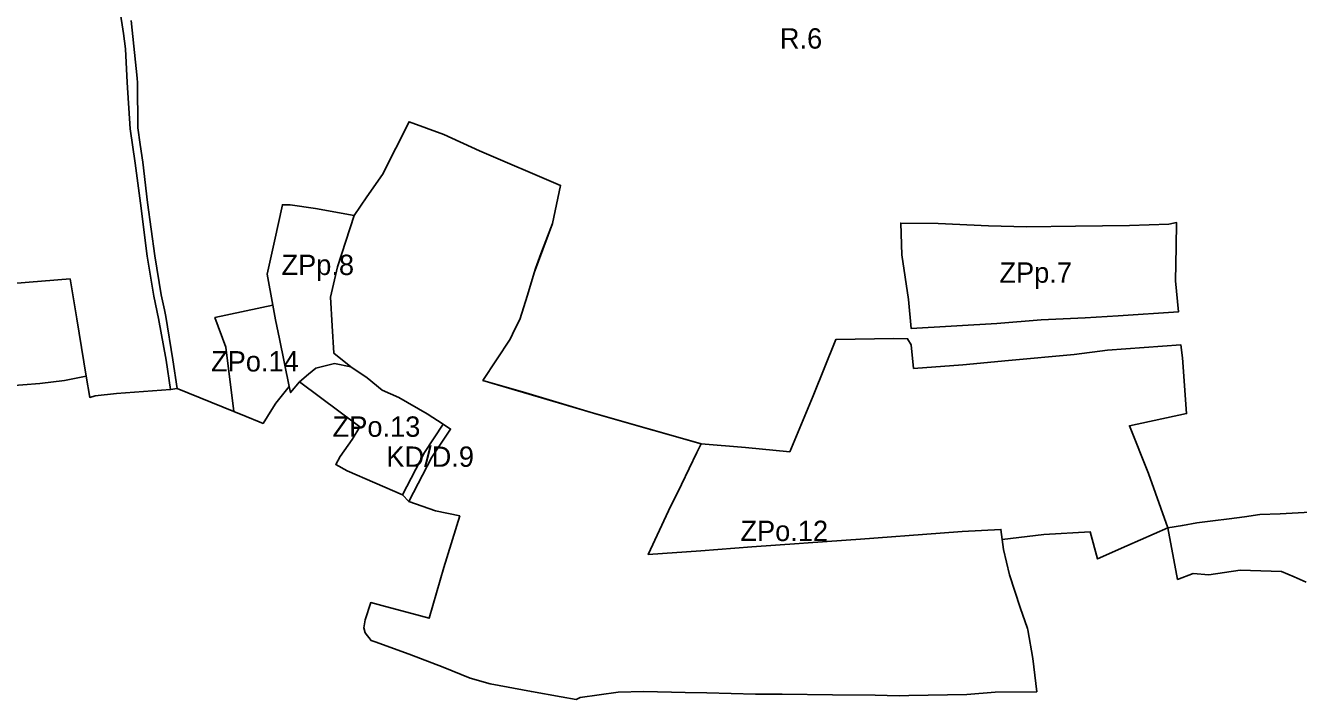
# Model space of a CAD drawing. Extents: x 7418114 to 7422197, y 5546299 to 5548348.
# Drawn here: x 7419820 to 7420446, y 5546299 to 5546631 of the extents above; entities that cross this region are included whole.
import ezdxf

# ---------------------------------------------------------------- set-up
doc = ezdxf.new("R2010")
doc.units = 0
for name, color, linetype in [('_ZWIERZYNIEC_KS_JOZEFA', 7, 'Continuous'), ('linie_rozgraniczajace', 7, 'Continuous'), ('oznaczenia_przeznaczen', 7, 'Continuous')]:
    doc.layers.add(name, color=color, linetype=linetype)

msp = doc.modelspace()

# ---------------------------------------------------------------- linework, layer by layer
at = {"layer": '_ZWIERZYNIEC_KS_JOZEFA'}
msp.add_lwpolyline([(7420152.57, 5546424.98), (7420151.12, 5546422.02), (7420150.52, 5546420.73), (7420142.88, 5546404.96), (7420136.59, 5546391.96), (7420126.57, 5546370.49), (7420152.36, 5546372.38), (7420177.52, 5546374.22), (7420200.71, 5546375.92), (7420205.17, 5546376.24), (7420231, 5546378.13), (7420270.1, 5546381), (7420280.84, 5546381.78), (7420299.93, 5546382.88), (7420301.18, 5546372.98), (7420304.22, 5546360.46), (7420309.35, 5546344.39), (7420313.03, 5546334.19), (7420313.15, 5546333.48), (7420315.57, 5546319.31), (7420317.54, 5546303.05), (7420297.18, 5546302.85), (7420283.11, 5546301.7), (7420254.72, 5546301.21), (7420249.89, 5546301.08), (7420238.05, 5546301.39), (7420217.1, 5546301.57), (7420192.37, 5546301.9), (7420179.3, 5546301.88), (7420155.44, 5546302.47), (7420144.69, 5546302.65), (7420124.44, 5546303.07), (7420111.75, 5546302.85), (7420093.03, 5546300.12), (7420091.21, 5546299.19), (7420083.78, 5546300.49), (7420069.15, 5546303.11), (7420048.91, 5546306.9), (7420038.98, 5546309.72), (7420025.8, 5546315.1), (7420009.07, 5546321.57), (7419992.39, 5546327.62), (7419990.31, 5546328.23), (7419987.45, 5546331.93), (7419986.83, 5546334.45), (7419987.38, 5546338.32), (7419990.16, 5546346.84), (7419995.56, 5546345.46), (7420014.62, 5546340.3), (7420018.87, 5546339.16), (7420026.17, 5546364.1), (7420033.94, 5546389.52), (7420022.07, 5546391.97), (7420008.87, 5546396.67), (7420020.13, 5546418.42), (7420029.39, 5546432.22), (7420025.8, 5546434.63), (7420017.93, 5546439.72), (7420004.01, 5546447.66), (7419995.85, 5546451.33), (7419988.41, 5546457.41), (7419980.4, 5546462.82), (7419972.09, 5546469.49), (7419971.14, 5546482.94), (7419970.41, 5546497.14), (7419973.77, 5546512.03), (7419982.04, 5546537.27), (7419988.24, 5546546.42), (7419995.87, 5546557.39), (7420009.03, 5546583.33), (7420026.01, 5546577.16), (7420043.57, 5546569.1), (7420083.46, 5546552.02), (7420079.49, 5546533.33), (7420073.7, 5546518.45), (7420071.16, 5546511.24), (7420070.52, 5546509.07), (7420067.25, 5546497.99), (7420063.4, 5546486.1), (7420061.07, 5546481.37), (7420058.66, 5546476.5), (7420045.32, 5546456.16), (7420066.4, 5546450.05), (7420082.85, 5546445.04), (7420099.67, 5546440.03), (7420121.92, 5546433.6), (7420152.07, 5546425.13)], close=True, dxfattribs=at)
msp.add_lwpolyline([(7420450.08, 5546356.93), (7420444.11, 5546359.52), (7420437.9, 5546362.16), (7420417.56, 5546362.86), (7420402.1, 5546360.51), (7420394.45, 5546361.15), (7420386.82, 5546358.3), (7420381.96, 5546383.65), (7420389.15, 5546384.86), (7420396.33, 5546386.06), (7420404.2, 5546387.07), (7420412.07, 5546388.08), (7420419.66, 5546389.1), (7420427.24, 5546390.12), (7420437.19, 5546390.45), (7420446, 5546390.94), (7420454.82, 5546391.43)], dxfattribs=at)
at = {"layer": 'linie_rozgraniczajace'}
for p, q in [((7420025.8, 5546434.63), (7420029.39, 5546432.22)), ((7420005.83, 5546399.95), (7420008.87, 5546396.67))]:
    msp.add_line(p, q, dxfattribs=at)
for points in [[(7419865.88, 5546666.2), (7419866.48, 5546660.67), (7419866.94, 5546646.66), (7419866.77, 5546638.42), (7419868.7, 5546626.77), (7419869.62, 5546619.26), (7419870.47, 5546602.72), (7419871.85, 5546579.92), (7419874.28, 5546562.95), (7419876.97, 5546543.32), (7419880.2, 5546517.21), (7419883.54, 5546497.63), (7419885.88, 5546486.64), (7419889.62, 5546466.02), (7419891.75, 5546451.67), (7419865.22, 5546449.75), (7419854.72, 5546448.54), (7419852.03, 5546447.76), (7419850.29, 5546458.18), (7419845.6, 5546486.47), (7419842.35, 5546506.08), (7419799.96, 5546502.72)], [(7419872.34, 5546633.2), (7419875.32, 5546604.84), (7419875.56, 5546602.43), (7419875.71, 5546580.31), (7419876.85, 5546572.23), (7419878.1, 5546563.4), (7419880.43, 5546543.57), (7419883.96, 5546517.41), (7419887.06, 5546498.18), (7419888.71, 5546490.83), (7419889.43, 5546487.63), (7419892.87, 5546466.33), (7419894.92, 5546452.18), (7419891.75, 5546451.67), (7419889.62, 5546466.02), (7419885.88, 5546486.64), (7419883.54, 5546497.63), (7419880.2, 5546517.21), (7419876.97, 5546543.32), (7419874.28, 5546562.95), (7419871.85, 5546579.92), (7419870.47, 5546602.72), (7419869.62, 5546619.26), (7419868.7, 5546626.77), (7419866.77, 5546638.42)], [(7420389.24, 5546467.28), (7420388.34, 5546473.71), (7420352.41, 5546471.07), (7420335.88, 5546468.81), (7420303.72, 5546466), (7420281.22, 5546463.75), (7420256.98, 5546462.08), (7420255.78, 5546473.68), (7420254.1, 5546476.61), (7420247.37, 5546476.77), (7420218.79, 5546476.26), (7420207.64, 5546448.57), (7420196.15, 5546421.09), (7420174.44, 5546423.08), (7420152.57, 5546424.98), (7420099.67, 5546440.03), (7420045.32, 5546456.16), (7420058.66, 5546476.5), (7420061.07, 5546481.37), (7420063.4, 5546486.1), (7420067.25, 5546497.99), (7420070.52, 5546509.07), (7420079.49, 5546533.33), (7420083.46, 5546552.02), (7420043.57, 5546569.1), (7420026.01, 5546577.16), (7420009.03, 5546583.33), (7419995.87, 5546557.39), (7419988.24, 5546546.42), (7419982.04, 5546537.27), (7419962.98, 5546540.73), (7419950.53, 5546542.54), (7419946.71, 5546542.57), (7419942.78, 5546524.57), (7419939.28, 5546508.32), (7419941.96, 5546493.23), (7419913.52, 5546487.06), (7419918.88, 5546472.54), (7419922.82, 5546440.84), (7419894.92, 5546452.18), (7419892.87, 5546466.33), (7419889.43, 5546487.63), (7419888.71, 5546490.83), (7419887.06, 5546498.18), (7419883.96, 5546517.41), (7419880.43, 5546543.57), (7419878.1, 5546563.4), (7419876.85, 5546572.23), (7419875.71, 5546580.31), (7419875.56, 5546602.43), (7419875.32, 5546604.84), (7419872.34, 5546633.2)], [(7420025.8, 5546434.63), (7420017.93, 5546439.72), (7420004.01, 5546447.66), (7419995.85, 5546451.33), (7419988.41, 5546457.41), (7419980.4, 5546462.82), (7419972.37, 5546464.45), (7419963.09, 5546462.12), (7419959.6, 5546459.21), (7419955.16, 5546455.51), (7419950.72, 5546450.14), (7419950.05, 5546453.13), (7419945.36, 5546476.52), (7419943.27, 5546485.86), (7419941.96, 5546493.23), (7419939.28, 5546508.32), (7419942.78, 5546524.57), (7419946.71, 5546542.57), (7419950.53, 5546542.54), (7419962.98, 5546540.73), (7419982.04, 5546537.27), (7419977.91, 5546524.65), (7419973.77, 5546512.03), (7419970.41, 5546497.14), (7419971.14, 5546482.94), (7419972.09, 5546469.49), (7419980.4, 5546462.82)], [(7419799.96, 5546502.72), (7419842.35, 5546506.08), (7419845.6, 5546486.47), (7419850.29, 5546458.18), (7419839.65, 5546456.18), (7419827.5, 5546454.64), (7419810.71, 5546453.38)], [(7420045.32, 5546456.16), (7420099.67, 5546440.03), (7420152.57, 5546424.98), (7420174.44, 5546423.08), (7420196.15, 5546421.09), (7420207.64, 5546448.57), (7420218.79, 5546476.26), (7420247.37, 5546476.77), (7420254.1, 5546476.61), (7420255.78, 5546473.68), (7420256.98, 5546462.08), (7420281.22, 5546463.75), (7420303.72, 5546466), (7420335.88, 5546468.81), (7420352.41, 5546471.07), (7420388.34, 5546473.71), (7420389.24, 5546467.28), (7420391.22, 5546439.83), (7420363.12, 5546433.81), (7420372.42, 5546410.42), (7420381.96, 5546383.65), (7420361.82, 5546374.72), (7420347.44, 5546368.36), (7420343.82, 5546381.67), (7420321.09, 5546380.42), (7420300.57, 5546377.83)], [(7420454.82, 5546391.43), (7420446, 5546390.94), (7420437.19, 5546390.45), (7420427.24, 5546390.12), (7420419.66, 5546389.1), (7420412.07, 5546388.08), (7420404.2, 5546387.07), (7420396.33, 5546386.06), (7420389.15, 5546384.86), (7420381.96, 5546383.65), (7420372.42, 5546410.42), (7420363.12, 5546433.81), (7420391.22, 5546439.83), (7420389.24, 5546467.28)], [(7420008.87, 5546396.67), (7420020.13, 5546418.42), (7420029.39, 5546432.22)], [(7420300.57, 5546377.83), (7420299.93, 5546382.88), (7420280.84, 5546381.78), (7420270.1, 5546381), (7420231, 5546378.13), (7420205.17, 5546376.24), (7420200.71, 5546375.92), (7420177.52, 5546374.22), (7420152.36, 5546372.38), (7420126.57, 5546370.49), (7420136.59, 5546391.96), (7420142.88, 5546404.96), (7420150.52, 5546420.73), (7420151.12, 5546422.02), (7420152.57, 5546424.98)]]:
    msp.add_lwpolyline(points, dxfattribs=at)
for points in [[(7420251.22, 5546517.87), (7420250.69, 5546533.5), (7420269.02, 5546533.3), (7420293.77, 5546532.09), (7420312.46, 5546531.65), (7420336.66, 5546532), (7420363.08, 5546532.35), (7420382.43, 5546533.02), (7420386.33, 5546533.78), (7420386.17, 5546521.91), (7420385.75, 5546505.16), (7420387.22, 5546489.8), (7420357.55, 5546487.88), (7420341.33, 5546486.98), (7420319.72, 5546485.94), (7420297.88, 5546484.14), (7420255.75, 5546481.74), (7420254.49, 5546495.93)], [(7420251.22, 5546517.87), (7420254.49, 5546495.93), (7420255.75, 5546481.74), (7420297.88, 5546484.14), (7420319.72, 5546485.94), (7420341.33, 5546486.98), (7420357.55, 5546487.88), (7420387.22, 5546489.8), (7420385.75, 5546505.16), (7420386.17, 5546521.91), (7420386.33, 5546533.78), (7420382.43, 5546533.02), (7420363.08, 5546532.35), (7420336.66, 5546532), (7420312.46, 5546531.65), (7420293.77, 5546532.09), (7420269.02, 5546533.3), (7420250.69, 5546533.5)], [(7419913.52, 5546487.06), (7419941.96, 5546493.23), (7419943.27, 5546485.86), (7419945.36, 5546476.52), (7419950.05, 5546453.13), (7419943.45, 5546444.9), (7419941.52, 5546441.83), (7419937.26, 5546434.98), (7419935.26, 5546435.79), (7419928.9, 5546438.37), (7419922.82, 5546440.84), (7419918.88, 5546472.54)], [(7419955.16, 5546455.51), (7419959.6, 5546459.21), (7419963.09, 5546462.12), (7419972.37, 5546464.45), (7419980.4, 5546462.82), (7419988.41, 5546457.41), (7419995.85, 5546451.33), (7420004.01, 5546447.66), (7420017.93, 5546439.72), (7420025.8, 5546434.63), (7420016.62, 5546420.61), (7420005.83, 5546399.95), (7419978.49, 5546411.67), (7419972.94, 5546414.75), (7419975.19, 5546418.8), (7419980.99, 5546427.09), (7419984.82, 5546433.34)]]:
    msp.add_lwpolyline(points, close=True, dxfattribs=at)

# ---------------------------------------------------------------- texts
at = {"layer": 'oznaczenia_przeznaczen'}
for s, p in [('R.6', (7420191.28, 5546619.33)), ('ZPp.8', (7419946.28, 5546507.97)), ('ZPp.7', (7420299.2, 5546504.17)), ('ZPo.14', (7419911.66, 5546460.53)), ('ZPo.13', (7419971.42, 5546428.43)), ('KD/D.9', (7419997.81, 5546413.65)), ('ZPo.12', (7420171.87, 5546377.14))]:
    msp.add_text(s, height=10, dxfattribs=at).set_placement(p)

doc.saveas('drawing.dxf')
